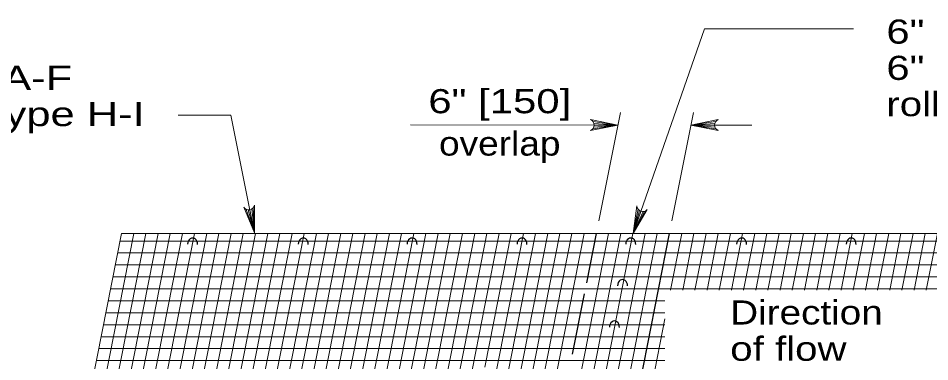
# Model space of a CAD drawing. Extents: x 1083.1 to 1117.1, y 719.4 to 741.4.
# Drawn here: x 1087.81 to 1093.72, y 730.09 to 732.31 of the extents above; entities that cross this region are included whole.
import ezdxf
from ezdxf.enums import TextEntityAlignment as Align

# ---------------------------------------------------------------- set-up
doc = ezdxf.new("R2010")
doc.units = 0
doc.header["$LTSCALE"] = 0.062
doc.layers.add('1', color=7, linetype='Continuous', lineweight=13)

msp = doc.modelspace()

# ---------------------------------------------------------------- linework, layer by layer
at = {"layer": '1'}
for p, q in [((1091.71467, 731.70267), (1091.57592, 731.00058)), ((1092.188, 731.70267), (1092.04925, 731.00058)), ((1091.53825, 731.64333), (1091.6985, 731.62092)), ((1092.33208, 731.64333), (1092.17192, 731.62092)), ((1090.35467, 731.62158), (1091.6985, 731.62092)), ((1091.53642, 731.59617), (1091.6985, 731.62092)), ((1091.5425, 731.60658), (1091.6985, 731.62092)), ((1091.54367, 731.63225), (1091.6985, 731.62092)), ((1091.54533, 731.62092), (1091.6985, 731.62092)), ((1092.32667, 731.63225), (1092.17192, 731.62092)), ((1092.17192, 731.62092), (1092.567, 731.62092)), ((1092.325, 731.62092), (1092.17192, 731.62092)), ((1092.32783, 731.60658), (1092.17192, 731.62092)), ((1092.334, 731.59617), (1092.17192, 731.62092)), ((1089.29133, 731.07558), (1089.3455, 730.92308)), ((1089.30325, 731.0725), (1089.3455, 730.92308)), ((1089.31467, 731.07317), (1089.3455, 730.92308)), ((1089.32825, 731.07883), (1089.3455, 730.92308)), ((1089.33717, 731.08692), (1089.3455, 730.92308)), ((1091.82908, 731.0775), (1091.79742, 730.91883)), ((1091.83775, 731.06875), (1091.79742, 730.91883)), ((1091.87425, 731.06375), (1091.79742, 730.91883)), ((1091.84792, 731.06342), (1091.79742, 730.91883)), ((1091.86242, 731.06142), (1091.79742, 730.91883)), ((1087.8955, 727.54358), (1088.5625, 730.91883)), ((1087.97433, 727.54358), (1088.64133, 730.91883)), ((1088.05325, 727.54358), (1088.72025, 730.91883)), ((1088.13208, 727.54358), (1088.79917, 730.91883)), ((1088.211, 727.54358), (1088.878, 730.91883)), ((1088.23275, 729.6495), (1088.48358, 730.91883)), ((1088.28983, 727.54358), (1088.95692, 730.91883)), ((1088.36875, 727.54358), (1089.03575, 730.91883)), ((1088.44767, 727.54358), (1089.11467, 730.91883)), ((1088.47408, 730.87075), (1090.83675, 730.87075)), ((1088.48358, 730.91883), (1094.15567, 730.91883)), ((1088.5265, 727.54358), (1089.1935, 730.91883)), ((1088.60542, 727.54358), (1089.27242, 730.91883)), ((1088.68417, 727.54358), (1089.35125, 730.91883)), ((1088.76308, 727.54358), (1089.43017, 730.91883)), ((1088.84192, 727.54358), (1089.50908, 730.91883)), ((1088.92083, 727.54358), (1089.58792, 730.91883)), ((1088.99967, 727.54358), (1089.66683, 730.91883)), ((1089.07858, 727.54358), (1089.74567, 730.91883)), ((1089.1575, 727.54358), (1089.82458, 730.91883)), ((1089.23633, 727.54358), (1089.90342, 730.91883)), ((1089.31525, 727.54358), (1089.98233, 730.91883)), ((1089.39408, 727.54358), (1090.06117, 730.91883)), ((1089.473, 727.54358), (1090.14008, 730.91883)), ((1089.55183, 727.54358), (1090.219, 730.91883)), ((1089.83808, 728.59267), (1090.29783, 730.91883)), ((1089.92708, 728.64408), (1090.37675, 730.91883)), ((1090.01525, 728.69083), (1090.45558, 730.91883)), ((1090.10242, 728.73317), (1090.5345, 730.91883)), ((1090.189, 728.77158), (1090.61333, 730.91883)), ((1090.27467, 728.80633), (1090.69225, 730.91883)), ((1090.35983, 728.83758), (1090.77108, 730.91883)), ((1090.83675, 730.85183), (1090.85, 730.91883)), ((1090.83675, 730.45267), (1090.92892, 730.91883)), ((1090.83675, 730.05392), (1091.00767, 730.91883)), ((1090.83675, 729.65483), (1091.08658, 730.91883)), ((1090.83675, 729.25567), (1091.16542, 730.91883)), ((1090.83675, 730.87075), (1094.14617, 730.87075)), ((1090.8575, 728.96117), (1091.24433, 730.91883)), ((1090.9385, 728.97233), (1091.32317, 730.91883)), ((1091.0175, 728.98092), (1091.40058, 730.91883)), ((1091.09925, 728.98733), (1091.48092, 730.91883)), ((1091.25817, 728.993), (1091.63867, 730.91883)), ((1091.33683, 728.9925), (1091.71758, 730.91883)), ((1091.41525, 728.98983), (1091.7965, 730.91883)), ((1091.49308, 728.98492), (1091.87533, 730.91883)), ((1091.53717, 730.87075), (1094.14617, 730.87075)), ((1091.57067, 728.97783), (1091.95425, 730.91883)), ((1092.03992, 730.55367), (1092.11208, 730.91883)), ((1092.11875, 730.55367), (1092.19092, 730.91883)), ((1092.19767, 730.55367), (1092.26983, 730.91883)), ((1092.27658, 730.55367), (1092.34875, 730.91883)), ((1092.35542, 730.55367), (1092.42758, 730.91883)), ((1092.43433, 730.55367), (1092.5065, 730.91883)), ((1092.51317, 730.55367), (1092.58533, 730.91883)), ((1092.59208, 730.55367), (1092.66425, 730.91883)), ((1092.671, 730.55367), (1092.74308, 730.91883)), ((1092.74983, 730.55367), (1092.822, 730.91883)), ((1092.82867, 730.55367), (1092.90083, 730.91883)), ((1092.90758, 730.55367), (1092.97975, 730.91883)), ((1092.9865, 730.55367), (1093.05867, 730.91883)), ((1093.06533, 730.55367), (1093.1375, 730.91883)), ((1093.14425, 730.55367), (1093.21642, 730.91883)), ((1093.22308, 730.55367), (1093.29525, 730.91883)), ((1093.302, 730.55367), (1093.37417, 730.91883)), ((1093.38083, 730.55367), (1093.453, 730.91883)), ((1093.45975, 730.55367), (1093.53192, 730.91883)), ((1093.53858, 730.55367), (1093.61075, 730.91883)), ((1093.6175, 730.55367), (1093.68967, 730.91883)), ((1093.69642, 730.55367), (1093.7685, 730.91883)), ((1090.44417, 728.86542), (1090.83675, 730.85183)), ((1088.45875, 730.79333), (1090.83675, 730.79333)), ((1090.83675, 730.79333), (1094.13083, 730.79333)), ((1088.44358, 730.716), (1090.83675, 730.716)), ((1090.83675, 730.716), (1094.11567, 730.716)), ((1088.42825, 730.63858), (1090.83675, 730.63858)), ((1090.83675, 730.63858), (1094.10033, 730.63858)), ((1088.413, 730.56125), (1090.83675, 730.56125)), ((1090.83675, 730.56125), (1094.08508, 730.56125)), ((1088.39767, 730.48383), (1090.83675, 730.48383)), ((1090.83675, 730.48383), (1092.00308, 730.48383)), ((1088.38233, 730.4065), (1090.83675, 730.4065)), ((1090.52792, 728.89025), (1090.83675, 730.45267)), ((1090.83675, 730.4065), (1092.00308, 730.4065)), ((1091.445, 727.54358), (1092.00308, 730.36758)), ((1088.36708, 730.32908), (1090.83675, 730.32908)), ((1090.83675, 730.32908), (1092.00308, 730.32908)), ((1088.35175, 730.25175), (1090.83675, 730.25175)), ((1090.83675, 730.25175), (1092.00308, 730.25175)), ((1088.3365, 730.17433), (1090.83675, 730.17433)), ((1090.83675, 730.17433), (1092.00308, 730.17433)), ((1088.32117, 730.097), (1090.83675, 730.097)), ((1090.83675, 730.097), (1092.00308, 730.097))]:
    msp.add_line(p, q, dxfattribs=at)
at = {"layer": '1', "lineweight": 25}
for p, q in [((1091.49658, 730.59967), (1091.55975, 730.91883)), ((1091.64767, 728.96867), (1092.03308, 730.91883)), ((1091.40558, 730.139), (1091.48267, 730.5295))]:
    msp.add_line(p, q, dxfattribs=at)
at = {"layer": '1'}
for points in [[(1091.79742, 730.91883), (1092.25992, 732.24308), (1093.22392, 732.24308)], [(1089.33867, 730.95208), (1089.19175, 731.6845), (1088.85, 731.6845)], [(1091.5215, 731.58558), (1091.6985, 731.62092), (1091.5215, 731.65633)], [(1092.34892, 731.58558), (1092.17192, 731.62092), (1092.34892, 731.65633)], [(1089.34458, 731.10358), (1089.3455, 730.92308), (1089.27525, 731.08933)], [(1091.88917, 731.07433), (1091.79742, 730.91883), (1091.82233, 731.09758)]]:
    msp.add_lwpolyline(points, dxfattribs=at)
for centre, start, end in [((1091.50722, 731.62098), 292.08605, 67.91218), ((1092.36317, 731.62098), 112.08782, 247.91395), ((1089.30697, 731.11048), 213.70634, 349.53247), ((1091.86044, 731.09947), 182.84855, 318.67468)]:
    msp.add_arc(centre, 0.0382, start, end, dxfattribs=at)
at = {"layer": '1', "lineweight": 25}
for centre in [(1088.94318, 730.84917), (1089.66009, 730.84917), (1090.36542, 730.84917), (1091.07767, 730.84917), (1091.78201, 730.84917), (1092.50008, 730.84917), (1093.20942, 730.84917), (1091.72895, 730.58083), (1091.67589, 730.31248)]:
    msp.add_ellipse(centre, major_axis=(0.00106, 0.04097), ratio=0.78812, start_param=4.7124002, end_param=7.8539929, dxfattribs=at)

# ---------------------------------------------------------------- texts
at = {"layer": '1'}
for s, width, p in [('6" [150] staples on', 1.3, (1093.43775, 732.148)), ('6" [150] centers across', 1.3, (1093.43775, 731.91333)), ('Type A-F', 1.35, (1087.00608, 731.8485)), ('roll to anchor top mat', 1.25, (1093.43775, 731.67867)), ('and Type H-I', 1.35, (1087.00608, 731.6145)), ('Direction', 1.2, (1092.42642, 730.33058)), ('of flow', 1.25, (1092.42642, 730.09592))]:
    msp.add_text(s, height=0.156, dxfattribs=dict(at, width=width)).set_placement(p)
for s, width, p in [('6" [150]', 1.3, (1090.93358, 731.69767)), ('overlap', 1.15, (1090.93354, 731.42367))]:
    msp.add_text(s, height=0.156, dxfattribs=dict(at, width=width)).set_placement(p, align=Align.CENTER)

doc.saveas('drawing.dxf')
